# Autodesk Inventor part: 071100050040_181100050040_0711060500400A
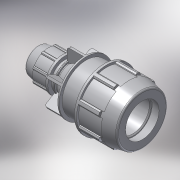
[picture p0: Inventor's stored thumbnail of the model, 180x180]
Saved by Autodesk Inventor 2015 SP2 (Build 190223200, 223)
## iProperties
Created: 2017-02
Part Number: 071100050040_181100050040_0711060500400A
Material: PVC-Piping
Description: PLASSON REDUCING COUPLER 50-40
Document SubType Name: Modeling
Designer: KIM
Mass: 92.6774 g
Surface Area: 199.44 cm^2
Volume: 66.1981 cm^3
Density: 1.4 g/cm^3
Appearance: Smooth - White
Author: KIM
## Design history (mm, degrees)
derived "07110.ipt"
feature "Solid1::07110.ipt"
tag "TaggingFeature1"
body "Solid1"
other parameters: "d4" = 15.33333, "d5" = 26.28571, "d7" = 96, "d9" = 26.28571, "d11" = 2.62857, "d12" = 76.8, "d13" = 120 deg, "d14" = 75, "d15" = 12 deg, "d16" = 86.4, "d18" = 2.5, "d19" = 35 deg, "d20" = 17.5 deg, "d21" = 89.28, "d23" = 0, "d25" = 360 deg, "d27" = 1.92, "d42" = 40.48, "d46" = 1.5, "d51" = 184, "d52" = 26.28571, "d53" = 12 deg, "d54" = 93, "d58" = 45, "d59" = 36, "d60" = 73.8, "d61" = 65.6, "d62" = 18.4, "d63" = 29.44, "d64" = 120 deg, "d65" = 82, "d68" = 13.14286, "d74" = 76.26, "d75" = 35 deg, "d76" = 17.5 deg, "d78" = 0, "d80" = 360 deg, "d85" = 1.64, "d88" = 0.8, "d93" = 84, "d94" = 67.2, "d97" = 3.03333, "d98" = 5.46667, "d99" = 0, "d100" = 3.84, "d102" = 360 deg, "d104" = 2, "d106" = 0, "d107" = 5.46667, "d108" = 0, "d109" = 5.46667, "d110" = 0, "E_" = 96, "H_" = 184, "l_" = 93, "E_1" = 82, "l_1" = 84, "d96" = 9.1
